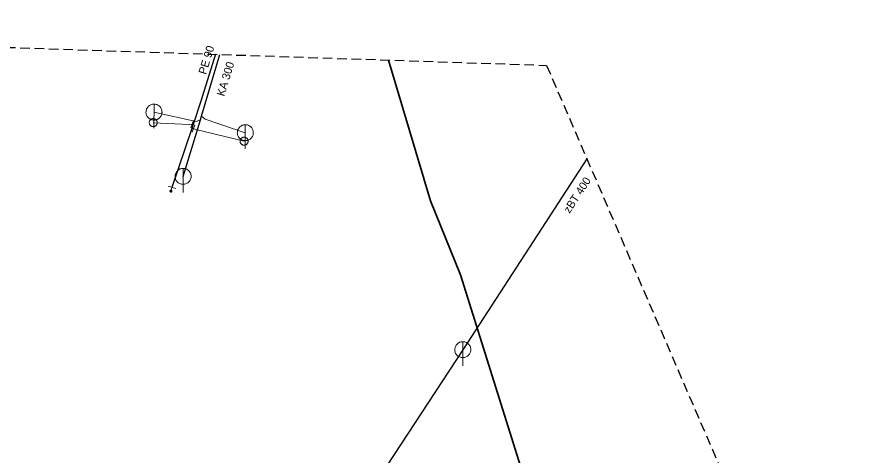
# Model space of a CAD drawing. Extents: x -774415 to -774100, y -975744 to -975502.
# Drawn here: x -774263.4 to -774156.5, y -975556.8 to -975501.9 of the extents above; entities that cross this region are included whole.
import ezdxf

# ---------------------------------------------------------------- set-up
doc = ezdxf.new("R2010")
doc.units = 0
doc.header["$LTSCALE"] = 0.4
doc.linetypes.add('MEDIUM_DASHED', pattern=[4.5, 3, -1.5])
for name, color, linetype, lineweight in [('1', 7, 'MEDIUM_DASHED', 25), ('11', 7, 'Continuous', 13), ('13', 7, 'Continuous', 13), ('14', 7, 'Continuous', 13), ('17', 7, 'Continuous', 25), ('22', 7, 'Continuous', 13), ('23', 7, 'Continuous', 13), ('34', 7, 'Continuous', 13), ('9', 7, 'Continuous', 13)]:
    doc.layers.add(name, color=color, linetype=linetype, lineweight=lineweight)

msp = doc.modelspace()

# ---------------------------------------------------------------- linework, layer by layer
at = {"layer": '1'}
msp.add_lwpolyline([(-774414.714, -975561.823), (-774378.138, -975501.935), (-774197.267, -975507.964), (-774100.401, -975732.645), (-774205.708, -975744.301), (-774260.773, -975651.856)], close=True, dxfattribs=at)
at = {"layer": '11'}
for points in [[(-774246.287, -975513.81), (-774241.01, -975514.989), (-774240.472, -975514.757)], [(-774234.883, -975516.38), (-774239.89, -975514.69), (-774240.359, -975514.334)]]:
    msp.add_lwpolyline(points, dxfattribs=at)
at = {"layer": '13'}
for points in [[(-774241.51, -975515.32), (-774241.88, -975515.347), (-774246.405, -975515.142)], [(-774241.359, -975515.859), (-774241.046, -975515.992), (-774235.01, -975517.43)]]:
    msp.add_lwpolyline(points, dxfattribs=at)
at = {"layer": '14'}
for p, q in [((-774241.379, -975515.37), (-774241.51, -975515.32)), ((-774241.559, -975515.87), (-774241.359, -975515.859)), ((-774244.05, -975523.21), (-774244.17, -975523.68))]:
    msp.add_line(p, q, dxfattribs=at)
at = {"layer": '14', "lineweight": 25}
for p, q in [((-774192.233, -975519.639), (-774207.729, -975543.497)), ((-774207.729, -975543.497), (-774234.913, -975584.951))]:
    msp.add_line(p, q, dxfattribs=at)
msp.add_lwpolyline([(-774242.653, -975521.836), (-774240.472, -975514.757), (-774240.359, -975514.334), (-774238.077, -975506.603)], dxfattribs=at)
at = {"layer": '17'}
msp.add_lwpolyline([(-774238.62, -975506.585), (-774240.449, -975512.43), (-774241.379, -975515.37), (-774241.559, -975515.87), (-774244.05, -975523.21)], dxfattribs=at)
at = {"layer": '17', "lineweight": 35}
msp.add_lwpolyline([(-774217.009, -975507.306), (-774211.739, -975524.879), (-774208.02, -975534.129), (-774200.302, -975558.73), (-774159.333, -975659.052), (-774159.853, -975667.971), (-774158.147, -975697.895), (-774164.627, -975739.754)], dxfattribs=at)
at = {"layer": '22'}
for p, q in [((-774246.287, -975515.81), (-774246.286, -975512.81)), ((-774234.883, -975518.38), (-774234.882, -975515.38)), ((-774242.653, -975523.836), (-774242.652, -975520.836)), ((-774207.729, -975545.497), (-774207.728, -975542.497))]:
    msp.add_line(p, q, dxfattribs=at)
for points in [[(-774245.287, -975513.81), (-774245.292, -975513.701), (-774245.31, -975513.593), (-774245.34, -975513.487), (-774245.38, -975513.386), (-774245.432, -975513.289), (-774245.494, -975513.199), (-774245.566, -975513.116), (-774245.646, -975513.042), (-774245.734, -975512.976), (-774245.828, -975512.921), (-774245.928, -975512.876), (-774246.033, -975512.843), (-774246.14, -975512.821), (-774246.249, -975512.811), (-774246.359, -975512.813), (-774246.467, -975512.827), (-774246.574, -975512.852), (-774246.677, -975512.889), (-774246.775, -975512.938), (-774246.867, -975512.996), (-774246.953, -975513.065), (-774247.03, -975513.142), (-774247.099, -975513.228), (-774247.158, -975513.32), (-774247.206, -975513.418), (-774247.243, -975513.521), (-774247.269, -975513.628), (-774247.283, -975513.736), (-774247.286, -975513.846), (-774247.276, -975513.955), (-774247.255, -975514.062), (-774247.221, -975514.166), (-774247.177, -975514.266), (-774247.122, -975514.361), (-774247.056, -975514.449), (-774246.982, -975514.529), (-774246.899, -975514.601), (-774246.809, -975514.663), (-774246.713, -975514.715), (-774246.611, -975514.756), (-774246.506, -975514.786), (-774246.398, -975514.804), (-774246.288, -975514.81), (-774246.179, -975514.804), (-774246.071, -975514.786), (-774245.966, -975514.757), (-774245.864, -975514.716), (-774245.767, -975514.664), (-774245.677, -975514.602), (-774245.594, -975514.531), (-774245.519, -975514.451), (-774245.454, -975514.363), (-774245.398, -975514.269), (-774245.354, -975514.169), (-774245.32, -975514.065), (-774245.298, -975513.957), (-774245.288, -975513.848)], [(-774233.883, -975516.38), (-774233.888, -975516.271), (-774233.906, -975516.163), (-774233.936, -975516.057), (-774233.976, -975515.956), (-774234.028, -975515.859), (-774234.09, -975515.769), (-774234.162, -975515.686), (-774234.242, -975515.612), (-774234.33, -975515.546), (-774234.424, -975515.491), (-774234.524, -975515.446), (-774234.629, -975515.413), (-774234.736, -975515.391), (-774234.845, -975515.381), (-774234.955, -975515.383), (-774235.063, -975515.397), (-774235.17, -975515.422), (-774235.273, -975515.459), (-774235.371, -975515.508), (-774235.463, -975515.566), (-774235.549, -975515.635), (-774235.626, -975515.712), (-774235.695, -975515.798), (-774235.754, -975515.89), (-774235.802, -975515.988), (-774235.839, -975516.091), (-774235.865, -975516.198), (-774235.879, -975516.306), (-774235.882, -975516.416), (-774235.872, -975516.525), (-774235.851, -975516.632), (-774235.817, -975516.736), (-774235.773, -975516.836), (-774235.718, -975516.931), (-774235.652, -975517.019), (-774235.578, -975517.099), (-774235.495, -975517.171), (-774235.405, -975517.233), (-774235.309, -975517.285), (-774235.207, -975517.326), (-774235.102, -975517.356), (-774234.994, -975517.374), (-774234.884, -975517.38), (-774234.775, -975517.374), (-774234.667, -975517.356), (-774234.562, -975517.327), (-774234.46, -975517.286), (-774234.363, -975517.234), (-774234.273, -975517.172), (-774234.19, -975517.101), (-774234.115, -975517.021), (-774234.05, -975516.933), (-774233.994, -975516.839), (-774233.95, -975516.739), (-774233.916, -975516.635), (-774233.894, -975516.527), (-774233.884, -975516.418)], [(-774241.653, -975521.836), (-774241.658, -975521.727), (-774241.676, -975521.619), (-774241.706, -975521.513), (-774241.746, -975521.412), (-774241.798, -975521.315), (-774241.86, -975521.225), (-774241.932, -975521.142), (-774242.012, -975521.068), (-774242.1, -975521.002), (-774242.194, -975520.947), (-774242.294, -975520.902), (-774242.399, -975520.869), (-774242.506, -975520.847), (-774242.615, -975520.837), (-774242.725, -975520.839), (-774242.833, -975520.853), (-774242.94, -975520.878), (-774243.043, -975520.915), (-774243.141, -975520.964), (-774243.233, -975521.022), (-774243.319, -975521.091), (-774243.396, -975521.168), (-774243.465, -975521.254), (-774243.524, -975521.346), (-774243.572, -975521.444), (-774243.609, -975521.547), (-774243.635, -975521.654), (-774243.649, -975521.762), (-774243.652, -975521.872), (-774243.642, -975521.981), (-774243.621, -975522.088), (-774243.587, -975522.192), (-774243.543, -975522.292), (-774243.488, -975522.387), (-774243.422, -975522.475), (-774243.348, -975522.555), (-774243.265, -975522.627), (-774243.175, -975522.689), (-774243.079, -975522.741), (-774242.977, -975522.782), (-774242.872, -975522.812), (-774242.764, -975522.83), (-774242.654, -975522.836), (-774242.545, -975522.83), (-774242.437, -975522.812), (-774242.332, -975522.783), (-774242.23, -975522.742), (-774242.133, -975522.69), (-774242.043, -975522.628), (-774241.96, -975522.557), (-774241.885, -975522.477), (-774241.82, -975522.389), (-774241.764, -975522.295), (-774241.72, -975522.195), (-774241.686, -975522.091), (-774241.664, -975521.983), (-774241.654, -975521.874)], [(-774206.729, -975543.497), (-774206.734, -975543.388), (-774206.752, -975543.28), (-774206.782, -975543.174), (-774206.822, -975543.073), (-774206.874, -975542.976), (-774206.936, -975542.886), (-774207.008, -975542.803), (-774207.088, -975542.729), (-774207.176, -975542.663), (-774207.27, -975542.608), (-774207.37, -975542.563), (-774207.475, -975542.53), (-774207.582, -975542.508), (-774207.691, -975542.498), (-774207.801, -975542.5), (-774207.909, -975542.514), (-774208.016, -975542.539), (-774208.119, -975542.576), (-774208.217, -975542.625), (-774208.309, -975542.683), (-774208.395, -975542.752), (-774208.472, -975542.829), (-774208.541, -975542.915), (-774208.6, -975543.007), (-774208.648, -975543.105), (-774208.685, -975543.208), (-774208.711, -975543.315), (-774208.725, -975543.423), (-774208.728, -975543.533), (-774208.718, -975543.642), (-774208.697, -975543.749), (-774208.663, -975543.853), (-774208.619, -975543.953), (-774208.564, -975544.048), (-774208.498, -975544.136), (-774208.424, -975544.216), (-774208.341, -975544.288), (-774208.251, -975544.35), (-774208.155, -975544.402), (-774208.053, -975544.443), (-774207.948, -975544.473), (-774207.84, -975544.491), (-774207.73, -975544.497), (-774207.621, -975544.491), (-774207.513, -975544.473), (-774207.408, -975544.444), (-774207.306, -975544.403), (-774207.209, -975544.351), (-774207.119, -975544.289), (-774207.036, -975544.218), (-774206.961, -975544.138), (-774206.896, -975544.05), (-774206.84, -975543.956), (-774206.796, -975543.856), (-774206.762, -975543.752), (-774206.74, -975543.644), (-774206.73, -975543.535)]]:
    msp.add_lwpolyline(points, close=True, dxfattribs=at)
at = {"layer": '23'}
for points in [[(-774246.073, -975514.726), (-774246.115, -975514.696), (-774246.162, -975514.67), (-774246.209, -975514.649), (-774246.26, -975514.635), (-774246.311, -975514.626), (-774246.363, -975514.62), (-774246.415, -975514.622), (-774246.467, -975514.628), (-774246.519, -975514.639), (-774246.568, -975514.657), (-774246.616, -975514.679), (-774246.66, -975514.705), (-774246.702, -975514.738), (-774246.74, -975514.772), (-774246.774, -975514.812), (-774246.805, -975514.856), (-774246.83, -975514.902), (-774246.85, -975514.95), (-774246.865, -975515), (-774246.875, -975515.051), (-774246.88, -975515.102), (-774246.88, -975515.156), (-774246.873, -975515.208), (-774246.86, -975515.258), (-774246.843, -975515.307), (-774246.822, -975515.354), (-774246.794, -975515.4), (-774246.762, -975515.441), (-774246.727, -975515.479), (-774246.688, -975515.514), (-774246.645, -975515.544), (-774246.599, -975515.57), (-774246.55, -975515.59), (-774246.501, -975515.605), (-774246.45, -975515.614), (-774246.398, -975515.62), (-774246.344, -975515.618), (-774246.294, -975515.612), (-774246.241, -975515.6)], [(-774246.88, -975515.102), (-774246.88, -975515.156), (-774246.873, -975515.208), (-774246.86, -975515.258), (-774246.843, -975515.307), (-774246.822, -975515.354), (-774246.794, -975515.4), (-774246.762, -975515.441), (-774246.727, -975515.479), (-774246.688, -975515.514), (-774246.645, -975515.544), (-774246.599, -975515.57), (-774246.55, -975515.59), (-774246.501, -975515.605), (-774246.45, -975515.614), (-774246.398, -975515.62), (-774246.344, -975515.618), (-774246.294, -975515.612), (-774246.241, -975515.6), (-774246.193, -975515.584), (-774246.145, -975515.562), (-774246.1, -975515.533), (-774246.058, -975515.502), (-774246.02, -975515.466), (-774245.985, -975515.427), (-774245.956, -975515.385), (-774245.931, -975515.338), (-774245.911, -975515.29), (-774245.895, -975515.24), (-774245.886, -975515.189), (-774245.881, -975515.137), (-774245.881, -975515.085), (-774245.888, -975515.032), (-774245.9, -975514.981), (-774245.917, -975514.932), (-774245.939, -975514.886), (-774245.966, -975514.841), (-774245.998, -975514.798), (-774246.034, -975514.759), (-774246.073, -975514.726)], [(-774246.85, -975514.95), (-774246.865, -975515), (-774246.875, -975515.051), (-774246.88, -975515.102)], [(-774246.241, -975515.6), (-774246.193, -975515.584), (-774246.145, -975515.562), (-774246.1, -975515.533), (-774246.058, -975515.502), (-774246.02, -975515.466), (-774245.985, -975515.427), (-774245.956, -975515.385), (-774245.931, -975515.338), (-774245.911, -975515.29), (-774245.895, -975515.24), (-774245.886, -975515.189), (-774245.881, -975515.137), (-774245.881, -975515.085), (-774245.888, -975515.032), (-774245.9, -975514.981), (-774245.917, -975514.932), (-774245.939, -975514.886), (-774245.966, -975514.841), (-774245.998, -975514.798), (-774246.034, -975514.759), (-774246.073, -975514.726), (-774246.115, -975514.696), (-774246.162, -975514.67), (-774246.209, -975514.649), (-774246.26, -975514.635), (-774246.311, -975514.626), (-774246.363, -975514.62), (-774246.415, -975514.622), (-774246.467, -975514.628), (-774246.519, -975514.639), (-774246.568, -975514.657), (-774246.616, -975514.679), (-774246.66, -975514.705), (-774246.702, -975514.738), (-774246.74, -975514.772), (-774246.774, -975514.812), (-774246.805, -975514.856), (-774246.83, -975514.902), (-774246.85, -975514.95)], [(-774234.55, -975517.557), (-774234.54, -975517.505), (-774234.537, -975517.452), (-774234.54, -975517.401), (-774234.547, -975517.349), (-774234.56, -975517.299), (-774234.579, -975517.249), (-774234.602, -975517.202), (-774234.629, -975517.159), (-774234.662, -975517.117), (-774234.698, -975517.08), (-774234.738, -975517.045), (-774234.783, -975517.016), (-774234.828, -975516.992), (-774234.876, -975516.973), (-774234.926, -975516.959), (-774234.98, -975516.95), (-774235.03, -975516.946), (-774235.084, -975516.949), (-774235.134, -975516.955), (-774235.185, -975516.968), (-774235.235, -975516.988), (-774235.282, -975517.011), (-774235.327, -975517.039), (-774235.368, -975517.07), (-774235.404, -975517.107), (-774235.438, -975517.148), (-774235.467, -975517.191), (-774235.491, -975517.237), (-774235.51, -975517.286), (-774235.525, -975517.336), (-774235.534, -975517.387), (-774235.537, -975517.44), (-774235.535, -975517.493), (-774235.528, -975517.544), (-774235.514, -975517.594), (-774235.496, -975517.643), (-774235.474, -975517.691), (-774235.445, -975517.735), (-774235.413, -975517.776)], [(-774235.084, -975516.949), (-774235.134, -975516.955), (-774235.185, -975516.968), (-774235.235, -975516.988), (-774235.282, -975517.011), (-774235.327, -975517.039), (-774235.368, -975517.07), (-774235.404, -975517.107), (-774235.438, -975517.148), (-774235.467, -975517.191), (-774235.491, -975517.237), (-774235.51, -975517.286), (-774235.525, -975517.336), (-774235.534, -975517.387), (-774235.537, -975517.44), (-774235.535, -975517.493), (-774235.528, -975517.544), (-774235.514, -975517.594), (-774235.496, -975517.643), (-774235.474, -975517.691), (-774235.445, -975517.735), (-774235.413, -975517.776), (-774235.377, -975517.813), (-774235.336, -975517.847), (-774235.294, -975517.876), (-774235.246, -975517.9), (-774235.198, -975517.919), (-774235.148, -975517.934), (-774235.097, -975517.942), (-774235.044, -975517.946), (-774234.991, -975517.944), (-774234.94, -975517.936), (-774234.889, -975517.923), (-774234.84, -975517.906), (-774234.793, -975517.881), (-774234.749, -975517.855), (-774234.708, -975517.822), (-774234.67, -975517.785), (-774234.636, -975517.745), (-774234.608, -975517.702)], [(-774235.413, -975517.776), (-774235.377, -975517.813), (-774235.336, -975517.847), (-774235.294, -975517.876), (-774235.246, -975517.9), (-774235.198, -975517.919), (-774235.148, -975517.934), (-774235.097, -975517.942), (-774235.044, -975517.946), (-774234.991, -975517.944), (-774234.94, -975517.936), (-774234.889, -975517.923), (-774234.84, -975517.906), (-774234.793, -975517.881), (-774234.749, -975517.855), (-774234.708, -975517.822), (-774234.67, -975517.785), (-774234.636, -975517.745), (-774234.608, -975517.702), (-774234.584, -975517.655), (-774234.564, -975517.607), (-774234.55, -975517.557), (-774234.54, -975517.505), (-774234.537, -975517.452), (-774234.54, -975517.401), (-774234.547, -975517.349), (-774234.56, -975517.299), (-774234.579, -975517.249), (-774234.602, -975517.202), (-774234.629, -975517.159), (-774234.662, -975517.117), (-774234.698, -975517.08), (-774234.738, -975517.045), (-774234.783, -975517.016), (-774234.828, -975516.992), (-774234.876, -975516.973), (-774234.926, -975516.959), (-774234.98, -975516.95), (-774235.03, -975516.946), (-774235.084, -975516.949)], [(-774234.608, -975517.702), (-774234.584, -975517.655), (-774234.564, -975517.607), (-774234.55, -975517.557)]]:
    msp.add_lwpolyline(points, dxfattribs=at)
at = {"layer": '34'}
for p, q in [((-774241.67, -975515.793), (-774241.348, -975514.846)), ((-774241.204, -975515.383), (-774241.513, -975516.334)), ((-774243.576, -975523.37), (-774244.523, -975523.048))]:
    msp.add_line(p, q, dxfattribs=at)
at = {"layer": '9'}
for points in [[(-774244.296, -975523.68), (-774244.296, -975523.693), (-774244.294, -975523.706), (-774244.291, -975523.719), (-774244.286, -975523.731), (-774244.28, -975523.743), (-774244.273, -975523.754), (-774244.265, -975523.764), (-774244.255, -975523.774), (-774244.245, -975523.782), (-774244.234, -975523.789), (-774244.222, -975523.795), (-774244.21, -975523.8), (-774244.197, -975523.803), (-774244.184, -975523.805), (-774244.171, -975523.807), (-774244.158, -975523.806), (-774244.145, -975523.804), (-774244.132, -975523.801), (-774244.12, -975523.796), (-774244.108, -975523.79), (-774244.097, -975523.783), (-774244.087, -975523.775), (-774244.077, -975523.765), (-774244.069, -975523.755), (-774244.062, -975523.744), (-774244.056, -975523.732), (-774244.051, -975523.72), (-774244.048, -975523.707), (-774244.046, -975523.694), (-774244.044, -975523.681), (-774244.045, -975523.668), (-774244.047, -975523.655), (-774244.05, -975523.642), (-774244.055, -975523.63), (-774244.061, -975523.618), (-774244.068, -975523.607), (-774244.076, -975523.597), (-774244.086, -975523.587), (-774244.096, -975523.579), (-774244.107, -975523.572), (-774244.119, -975523.566), (-774244.131, -975523.561), (-774244.144, -975523.558), (-774244.157, -975523.556), (-774244.17, -975523.555), (-774244.183, -975523.555), (-774244.196, -975523.557), (-774244.209, -975523.56), (-774244.221, -975523.565), (-774244.233, -975523.571), (-774244.244, -975523.578), (-774244.254, -975523.586), (-774244.264, -975523.596), (-774244.272, -975523.606), (-774244.279, -975523.617), (-774244.285, -975523.629), (-774244.29, -975523.641), (-774244.293, -975523.654), (-774244.295, -975523.667)], [(-774244.276, -975523.68), (-774244.277, -975523.691), (-774244.275, -975523.702), (-774244.272, -975523.713), (-774244.268, -975523.723), (-774244.263, -975523.733), (-774244.257, -975523.742), (-774244.25, -975523.751), (-774244.242, -975523.759), (-774244.233, -975523.766), (-774244.224, -975523.772), (-774244.214, -975523.777), (-774244.204, -975523.781), (-774244.193, -975523.784), (-774244.182, -975523.787), (-774244.171, -975523.787), (-774244.16, -975523.787), (-774244.149, -975523.785), (-774244.138, -975523.782), (-774244.128, -975523.778), (-774244.118, -975523.773), (-774244.109, -975523.767), (-774244.1, -975523.76), (-774244.092, -975523.752), (-774244.085, -975523.743), (-774244.079, -975523.734), (-774244.074, -975523.724), (-774244.07, -975523.714), (-774244.067, -975523.703), (-774244.065, -975523.692), (-774244.064, -975523.681), (-774244.064, -975523.67), (-774244.066, -975523.659), (-774244.069, -975523.648), (-774244.073, -975523.638), (-774244.078, -975523.628), (-774244.084, -975523.619), (-774244.091, -975523.61), (-774244.099, -975523.602), (-774244.108, -975523.595), (-774244.117, -975523.589), (-774244.127, -975523.584), (-774244.137, -975523.58), (-774244.148, -975523.577), (-774244.159, -975523.575), (-774244.17, -975523.575), (-774244.181, -975523.574), (-774244.192, -975523.576), (-774244.203, -975523.579), (-774244.213, -975523.583), (-774244.223, -975523.588), (-774244.232, -975523.594), (-774244.241, -975523.601), (-774244.249, -975523.609), (-774244.256, -975523.618), (-774244.262, -975523.627), (-774244.267, -975523.637), (-774244.271, -975523.647), (-774244.274, -975523.658), (-774244.276, -975523.669)], [(-774244.257, -975523.68), (-774244.257, -975523.689), (-774244.256, -975523.698), (-774244.253, -975523.707), (-774244.25, -975523.715), (-774244.246, -975523.723), (-774244.241, -975523.731), (-774244.235, -975523.738), (-774244.229, -975523.744), (-774244.222, -975523.75), (-774244.214, -975523.755), (-774244.206, -975523.759), (-774244.198, -975523.762), (-774244.189, -975523.765), (-774244.18, -975523.766), (-774244.171, -975523.768), (-774244.162, -975523.767), (-774244.153, -975523.766), (-774244.144, -975523.763), (-774244.136, -975523.76), (-774244.128, -975523.756), (-774244.12, -975523.751), (-774244.113, -975523.745), (-774244.107, -975523.739), (-774244.101, -975523.732), (-774244.096, -975523.724), (-774244.092, -975523.716), (-774244.089, -975523.708), (-774244.086, -975523.699), (-774244.085, -975523.69), (-774244.083, -975523.681), (-774244.084, -975523.672), (-774244.085, -975523.663), (-774244.088, -975523.654), (-774244.091, -975523.646), (-774244.095, -975523.638), (-774244.1, -975523.63), (-774244.106, -975523.623), (-774244.112, -975523.617), (-774244.119, -975523.611), (-774244.127, -975523.606), (-774244.135, -975523.602), (-774244.143, -975523.599), (-774244.152, -975523.596), (-774244.161, -975523.595), (-774244.17, -975523.594), (-774244.179, -975523.594), (-774244.188, -975523.595), (-774244.197, -975523.598), (-774244.205, -975523.601), (-774244.213, -975523.605), (-774244.221, -975523.61), (-774244.228, -975523.616), (-774244.234, -975523.622), (-774244.24, -975523.629), (-774244.245, -975523.637), (-774244.249, -975523.645), (-774244.252, -975523.653), (-774244.255, -975523.662), (-774244.256, -975523.671)], [(-774244.237, -975523.68), (-774244.237, -975523.687), (-774244.236, -975523.694), (-774244.235, -975523.701), (-774244.232, -975523.707), (-774244.229, -975523.713), (-774244.225, -975523.719), (-774244.221, -975523.725), (-774244.216, -975523.73), (-774244.21, -975523.734), (-774244.204, -975523.738), (-774244.198, -975523.741), (-774244.192, -975523.744), (-774244.185, -975523.745), (-774244.178, -975523.748), (-774244.171, -975523.748), (-774244.164, -975523.748), (-774244.157, -975523.746), (-774244.15, -975523.745), (-774244.144, -975523.742), (-774244.137, -975523.739), (-774244.132, -975523.735), (-774244.126, -975523.731), (-774244.121, -975523.726), (-774244.117, -975523.72), (-774244.113, -975523.714), (-774244.11, -975523.708), (-774244.107, -975523.702), (-774244.105, -975523.695), (-774244.104, -975523.688), (-774244.103, -975523.681), (-774244.103, -975523.674), (-774244.104, -975523.667), (-774244.106, -975523.66), (-774244.109, -975523.654), (-774244.112, -975523.647), (-774244.116, -975523.642), (-774244.12, -975523.636), (-774244.125, -975523.631), (-774244.131, -975523.627), (-774244.136, -975523.623), (-774244.143, -975523.62), (-774244.149, -975523.617), (-774244.156, -975523.615), (-774244.163, -975523.614), (-774244.17, -975523.614), (-774244.177, -975523.614), (-774244.184, -975523.614), (-774244.191, -975523.616), (-774244.197, -975523.619), (-774244.203, -975523.622), (-774244.209, -975523.626), (-774244.215, -975523.63), (-774244.22, -975523.635), (-774244.224, -975523.641), (-774244.228, -975523.646), (-774244.231, -975523.653), (-774244.234, -975523.659), (-774244.235, -975523.666), (-774244.237, -975523.673)], [(-774244.217, -975523.68), (-774244.217, -975523.685), (-774244.217, -975523.69), (-774244.216, -975523.695), (-774244.214, -975523.699), (-774244.212, -975523.704), (-774244.209, -975523.708), (-774244.206, -975523.711), (-774244.202, -975523.715), (-774244.199, -975523.718), (-774244.195, -975523.721), (-774244.19, -975523.723), (-774244.186, -975523.725), (-774244.181, -975523.726), (-774244.176, -975523.728), (-774244.171, -975523.728), (-774244.166, -975523.728), (-774244.161, -975523.727), (-774244.156, -975523.726), (-774244.152, -975523.724), (-774244.147, -975523.722), (-774244.143, -975523.719), (-774244.139, -975523.716), (-774244.136, -975523.712), (-774244.133, -975523.709), (-774244.13, -975523.705), (-774244.128, -975523.7), (-774244.126, -975523.696), (-774244.125, -975523.691), (-774244.124, -975523.686), (-774244.123, -975523.681), (-774244.123, -975523.676), (-774244.124, -975523.671), (-774244.125, -975523.666), (-774244.127, -975523.662), (-774244.129, -975523.657), (-774244.132, -975523.653), (-774244.135, -975523.649), (-774244.138, -975523.646), (-774244.142, -975523.643), (-774244.146, -975523.64), (-774244.151, -975523.638), (-774244.155, -975523.636), (-774244.16, -975523.635), (-774244.165, -975523.634), (-774244.17, -975523.634), (-774244.175, -975523.634), (-774244.18, -975523.635), (-774244.185, -975523.635), (-774244.189, -975523.637), (-774244.194, -975523.639), (-774244.198, -975523.642), (-774244.201, -975523.645), (-774244.205, -975523.648), (-774244.208, -975523.652), (-774244.211, -975523.656), (-774244.213, -975523.661), (-774244.215, -975523.665), (-774244.216, -975523.67), (-774244.217, -975523.675)], [(-774244.197, -975523.68), (-774244.197, -975523.683), (-774244.198, -975523.686), (-774244.197, -975523.688), (-774244.196, -975523.691), (-774244.195, -975523.694), (-774244.193, -975523.696), (-774244.191, -975523.698), (-774244.189, -975523.7), (-774244.187, -975523.702), (-774244.185, -975523.704), (-774244.182, -975523.706), (-774244.179, -975523.707), (-774244.177, -975523.707), (-774244.174, -975523.708), (-774244.171, -975523.708), (-774244.168, -975523.708), (-774244.165, -975523.708), (-774244.162, -975523.707), (-774244.16, -975523.706), (-774244.157, -975523.705), (-774244.155, -975523.703), (-774244.152, -975523.701), (-774244.15, -975523.699), (-774244.149, -975523.697), (-774244.147, -975523.695), (-774244.146, -975523.692), (-774244.144, -975523.689), (-774244.144, -975523.687), (-774244.143, -975523.684), (-774244.142, -975523.681), (-774244.143, -975523.678), (-774244.143, -975523.675), (-774244.144, -975523.672), (-774244.145, -975523.67), (-774244.146, -975523.667), (-774244.148, -975523.665), (-774244.149, -975523.662), (-774244.151, -975523.66), (-774244.154, -975523.659), (-774244.156, -975523.657), (-774244.159, -975523.656), (-774244.161, -975523.655), (-774244.164, -975523.654), (-774244.167, -975523.654), (-774244.17, -975523.653), (-774244.173, -975523.654), (-774244.176, -975523.653), (-774244.178, -975523.655), (-774244.181, -975523.655), (-774244.184, -975523.656), (-774244.186, -975523.658), (-774244.188, -975523.659), (-774244.19, -975523.661), (-774244.192, -975523.664), (-774244.194, -975523.666), (-774244.195, -975523.669), (-774244.196, -975523.671), (-774244.197, -975523.674), (-774244.197, -975523.677)], [(-774244.178, -975523.68), (-774244.178, -975523.682), (-774244.178, -975523.682), (-774244.177, -975523.682), (-774244.177, -975523.684), (-774244.178, -975523.685), (-774244.176, -975523.685), (-774244.176, -975523.685), (-774244.176, -975523.687), (-774244.176, -975523.687), (-774244.175, -975523.688), (-774244.173, -975523.688), (-774244.173, -975523.688), (-774244.173, -975523.689), (-774244.171, -975523.689), (-774244.171, -975523.689), (-774244.17, -975523.689), (-774244.169, -975523.689), (-774244.169, -975523.688), (-774244.168, -975523.688), (-774244.166, -975523.688), (-774244.166, -975523.687), (-774244.166, -975523.687), (-774244.165, -975523.686), (-774244.165, -975523.686), (-774244.163, -975523.685), (-774244.163, -975523.684), (-774244.162, -975523.683), (-774244.162, -975523.683), (-774244.162, -975523.682), (-774244.162, -975523.681), (-774244.162, -975523.68), (-774244.162, -975523.679), (-774244.162, -975523.679), (-774244.163, -975523.678), (-774244.163, -975523.677), (-774244.164, -975523.676), (-774244.164, -975523.676), (-774244.165, -975523.675), (-774244.165, -975523.675), (-774244.166, -975523.674), (-774244.167, -975523.674), (-774244.168, -975523.673), (-774244.168, -975523.673), (-774244.169, -975523.673), (-774244.17, -975523.673), (-774244.171, -975523.673), (-774244.172, -975523.673), (-774244.172, -975523.673), (-774244.173, -975523.674), (-774244.174, -975523.673), (-774244.175, -975523.675), (-774244.175, -975523.675), (-774244.176, -975523.675), (-774244.176, -975523.675), (-774244.177, -975523.677), (-774244.177, -975523.678), (-774244.177, -975523.679), (-774244.178, -975523.679), (-774244.178, -975523.68)]]:
    msp.add_lwpolyline(points, close=True, dxfattribs=at)

# ---------------------------------------------------------------- texts
at = {"layer": '1'}
for s, rotation, p in [('PE 90 ', 73, (-774239.8, -975509.176)), ('KA 300', 73, (-774237.527, -975511.902)), ('zBT 400 ', 57, (-774194.391, -975526.526))]:
    msp.add_text(s, height=1, rotation=rotation, dxfattribs=at).set_placement(p)

doc.saveas('drawing.dxf')
